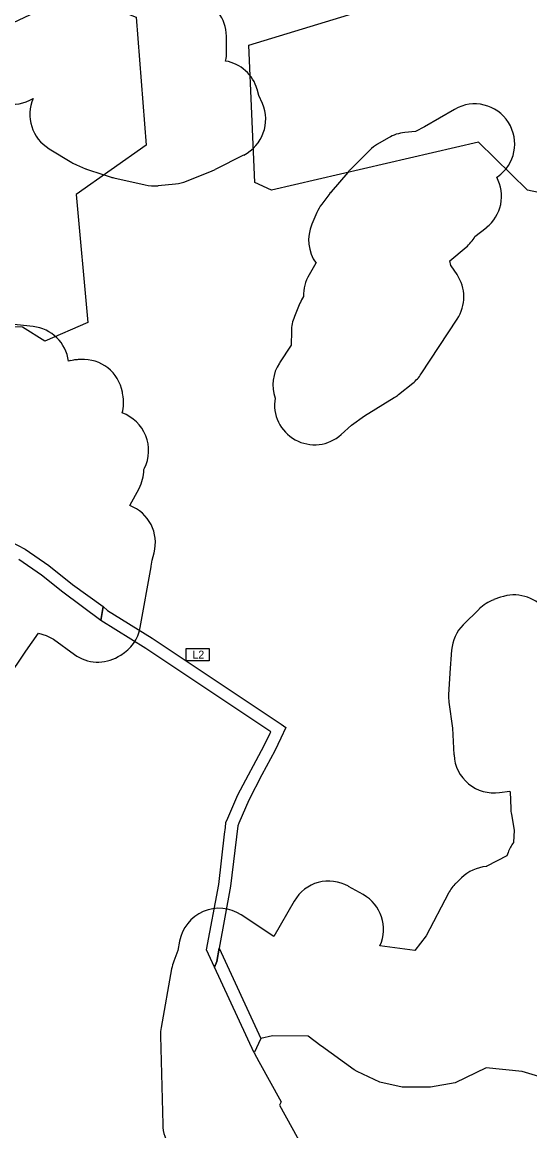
# Model space of a CAD drawing. Extents: x -547623 to -532764, y -1096714 to -1086523.
# Drawn here: x -544637 to -544003, y -1095778 to -1094393 of the extents above; entities that cross this region are included whole.
import ezdxf

# ---------------------------------------------------------------- set-up
doc = ezdxf.new("R2010")
doc.units = 0
for name, color, linetype in [('Vrstva 22', 7, 'Continuous'), ('Vrstva 23', 7, 'Continuous'), ('Vrstva 32', 7, 'Continuous'), ('Vrstva 33', 7, 'Continuous'), ('Vrstva 36', 7, 'Continuous')]:
    doc.layers.add(name, color=color, linetype=linetype)

msp = doc.modelspace()

# ---------------------------------------------------------------- linework, layer by layer
at = {"layer": 'Vrstva 22'}
for points in [[(-543560.2, -1094401.9), (-543572.9, -1094589), (-543554.8, -1094683.6), (-543653.3, -1094783), (-543676.2, -1094781), (-543835.1, -1094639.3), (-544005.7, -1094603.1), (-544067, -1094543.3), (-544325.4, -1094603.1), (-544346.2, -1094593.4), (-544353.7, -1094422.2), (-544152.6, -1094360.6), (-544163.2, -1094317.9), (-544141.9, -1094287.2), (-544146.7, -1094205.7), (-543991.6, -1094091.9), (-543560.2, -1094401.9)], [(-544569.4, -1094608.5), (-544554.7, -1094768.3), (-544608.7, -1094791.9), (-544636.4, -1094774.2), (-544680.5, -1094773.3), (-544758.2, -1094792.2), (-544897.7, -1094846.4), (-545208, -1094900.4), (-545244.6, -1094739.1), (-545204.8, -1094572.8), (-545046.9, -1094538.4), (-544985.5, -1094450.5), (-544820.5, -1094424), (-544727.5, -1094431.4), (-544569.8, -1094356.5), (-544494.7, -1094387.2), (-544482, -1094546.9), (-544569.4, -1094608.5)]]:
    msp.add_lwpolyline(points, dxfattribs=at)
at = {"layer": 'Vrstva 23'}
for p, q in [((-544381.5, -1094429.8), (-544381.7, -1094410.7)), ((-544145.7, -1094529.8), (-544159.1, -1094531.1)), ((-544179.3, -1094537.7), (-544192.9, -1094545.6)), ((-544603.2, -1094551.4), (-544574.9, -1094568.4)), ((-544395.6, -1094577.1), (-544360.1, -1094559.2)), ((-544203.1, -1094553.5), (-544227.6, -1094578.1)), ((-544569.1, -1094571.5), (-544557.6, -1094576.5)), ((-544552.7, -1094578.3), (-544526.8, -1094586.6)), ((-544522.6, -1094587.8), (-544483.3, -1094596.6)), ((-544431.8, -1094591.9), (-544399.5, -1094578.9)), ((-544230.3, -1094580.9), (-544251, -1094605.2)), ((-544467.1, -1094597.5), (-544445.3, -1094595.2)), ((-544252.8, -1094607.4), (-544262.7, -1094620.6)), ((-544268.9, -1094631.2), (-544275.1, -1094645.8)), ((-544071.4, -1094661.2), (-544057.2, -1094650)), ((-544269.9, -1094694.4), (-544278.5, -1094708.9)), ((-544093.7, -1094708.6), (-544101.1, -1094697.8)), ((-544285.5, -1094735.8), (-544285.7, -1094736.1)), ((-544289.9, -1094744.1), (-544296.9, -1094761.1)), ((-544138.5, -1094832.7), (-544093.4, -1094764.1)), ((-544623.2, -1094773.5), (-544659.1, -1094769.7)), ((-544572.9, -1094815.5), (-544576.1, -1094816.1)), ((-544563.6, -1094814.6), (-544566.8, -1094814.8)), ((-544166.7, -1094858.5), (-544148.9, -1094844.1)), ((-544484.9, -1094952.2), (-544484.1, -1094950.5)), ((-544502.4, -1094997), (-544490.9, -1094975.6)), ((-544489.5, -1095149.4), (-544475.8, -1095073.4)), ((-544039.3, -1095111.6), (-544047.6, -1095114.6)), ((-544066.1, -1095126.3), (-544086, -1095146.1)), ((-544100.5, -1095177.7), (-544102.7, -1095205.8)), ((-544517, -1095185.8), (-544513.5, -1095183.8)), ((-544102.8, -1095206.8), (-544104.3, -1095233)), ((-544211, -1095483), (-544229.2, -1095472.7)), ((-544088.1, -1095461.9), (-544095, -1095468.6)), ((-544297.2, -1095491.1), (-544322.7, -1095535.4)), ((-544322.7, -1095535.4), (-544363.3, -1095508.4)), ((-544450.2, -1095575.7), (-544463.4, -1095649.1)), ((-544464.2, -1095659.2), (-544461.4, -1095770))]:
    msp.add_line(p, q, dxfattribs=at)
for points in [[(-544336.8, -1094494.8), (-544341.1, -1094484.7), (-544343.3, -1094477.2)], [(-544096.9, -1094502.2), (-544134.2, -1094523.9), (-544145.7, -1094529.8)], [(-544044.1, -1094587.1), (-544043.1, -1094586.3)], [(-544101.5, -1094697.1), (-544102.6, -1094691.4), (-544082.5, -1094674.4)], [(-544300.6, -1094779.2), (-544301, -1094796.7), (-544315.6, -1094819)], [(-544511.1, -1094858.6), (-544511.4, -1094856.9), (-544511.6, -1094855.5)], [(-544238.3, -1094908.3), (-544225.4, -1094896.8), (-544209.2, -1094884.9), (-544172.1, -1094862.3)], [(-544475.7, -1095072.7), (-544474.5, -1095065.3), (-544472.1, -1095056.3)], [(-544671.5, -1095246.6), (-544663, -1095225.6), (-544656.1, -1095214.5), (-544632.5, -1095179), (-544616.6, -1095156.5), (-544606.9, -1095159.2), (-544597.9, -1095164.1), (-544571.6, -1095183.1)], [(-544103.9, -1095242.8), (-544099.4, -1095275.3), (-544097.6, -1095308.6)], [(-544040.6, -1095355.4), (-544028, -1095353.6), (-544027.4, -1095354.6), (-544026.6, -1095375.5)], [(-544025.8, -1095382.8), (-544022.3, -1095402.4), (-544023.3, -1095418)], [(-544029.9, -1095430.3), (-544031.4, -1095434.4), (-544056.7, -1095447.6)], [(-544104.5, -1095481.3), (-544132.2, -1095534.3), (-544146.4, -1095552.6), (-544190, -1095546.8)], [(-544440.2, -1095541.3), (-544442.3, -1095552.9), (-544447.5, -1095566.3)]]:
    msp.add_lwpolyline(points, dxfattribs=at)
for centre, start, end in [((-544431.7, -1094411.2), 0.569, 73.1837), ((-544431.5, -1094430.3), 346.6228, 0.569), ((-544391.3, -1094491.2), 16.2539, 80.278), ((-544649.3, -1094445.9), 216.0604, 301.6028), ((-544577.3, -1094508.6), 156.3156, 238.8279), ((-544382.7, -1094514.6), 296.8034, 23.3274), ((-544071.7, -1094545.4), 304.9305, 120.2555), ((-544154.1, -1094580.9), 95.7604, 120.2827), ((-544167.7, -1094588.8), 120.2827, 135.07), ((-544549.1, -1094525.7), 238.8279, 246.3706), ((-544537.5, -1094530.7), 246.3706, 252.2842), ((-544511.6, -1094539), 252.2842, 257.3321), ((-544418.2, -1094532.5), 291.9175, 296.8034), ((-544192.2, -1094613.4), 135.07, 139.5446), ((-544088.2, -1094610.7), 308.3187, 28.2454), ((-544472.4, -1094547.8), 257.3321, 276.0036), ((-544450.5, -1094545.5), 276.0036, 291.9175), ((-544213, -1094637.7), 139.5446, 142.7962), ((-544222.9, -1094650.8), 142.7962, 156.9105), ((-544229.1, -1094665.4), 156.9105, 215.4106), ((-544114.7, -1094636.2), 310.1661, 329.9934), ((-544142.5, -1094725.8), 34.0665, 34.9413), ((-544235.5, -1094734.4), 149.3079, 181.5851), ((-544135.2, -1094736.6), 326.639, 34.0665), ((-544243.6, -1094763.1), 147.2549, 157.6487), ((-544250.6, -1094780.1), 157.6487, 178.8948), ((-544628.6, -1094823.2), 7.5163, 83.8546), ((-544567.2, -1094865.3), 100.225, 103.6855), ((-544564, -1094864.7), 93.2095, 100.225), ((-544560.8, -1094864.5), 10.3889, 93.2095), ((-544273.7, -1094846.4), 146.8451, 199.0947), ((-544180.3, -1094805.2), 308.8939, 326.639), ((-544560.1, -1094868.4), 344.9547, 11.3099), ((-544271.7, -1094871.1), 170.3942, 311.8076), ((-544198.1, -1094819.6), 301.3801, 308.8939), ((-544529, -1094928.4), 333.7195, 69.9207), ((-544534.9, -1094952), 331.8145, 359.7902), ((-544520.5, -1095043.6), 345.3089, 68.7265), ((-544525.1, -1095064.6), 349.7927, 350.6729), ((-544022.4, -1095158.7), 39.675, 109.7016), ((-544030.8, -1095161.7), 109.7016, 134.8702), ((-544538.7, -1095140.6), 300.2869, 349.7927), ((-544050.7, -1095181.5), 134.8702, 175.6075), ((-544542.2, -1095142.6), 234.0894, 300.2869), ((-544052.8, -1095209.6), 175.6075, 176.7295), ((-544054.3, -1095235.9), 176.7295, 187.9009), ((-544047.6, -1095305.9), 183.0927, 278.0616), ((-543976.7, -1095373.8), 181.9744, 190.3322), ((-543983, -1095447.6), 143.7295, 159.7953), ((-544053.3, -1095497.8), 94.6652, 134.1575), ((-544033.5, -1095491.9), 117.6654, 118.5636), ((-544253.9, -1095516.1), 60.3534, 150.0364), ((-544060.2, -1095504.5), 134.1575, 152.3533), ((-544235.7, -1095526.5), 336.0277, 60.3534), ((-544391, -1095550), 56.3675, 169.8993), ((-544401, -1095584.5), 158.5572, 169.7687), ((-544414.2, -1095657.9), 169.7687, 181.4263), ((-544411.4, -1095768.8), 181.4263, 317.8953)]:
    msp.add_arc(centre, 50, start, end, dxfattribs=at)
at = {"layer": 'Vrstva 32'}
for points in [[(-544262.9, -1095672.3), (-544263.7, -1095671.7), (-544279.7, -1095660), (-544324.2, -1095659.4), (-544338.6, -1095662.6), (-544347, -1095680.5), (-544341.3, -1095691.5), (-544313.2, -1095741.8), (-544315.5, -1095746.1), (-544277.8, -1095813.9), (-544276.1, -1095826.4), (-544267.8, -1095831.7), (-544243.7, -1095841.7), (-544217.4, -1095853.4), (-544166.3, -1095879.5), (-544135.1, -1095899.1), (-544106, -1095928.4), (-543909.4, -1095790.9)], [(-543939.1, -1095725.8), (-544012.2, -1095704.1), (-544057.3, -1095699.3), (-544096, -1095718.2), (-544126.8, -1095723.3), (-544162.1, -1095723.3), (-544190.1, -1095717.2), (-544218.4, -1095703.9), (-544222.4, -1095702), (-544262.9, -1095672.3)]]:
    msp.add_lwpolyline(points, dxfattribs=at)
at = {"layer": 'Vrstva 33'}
for points in [[(-544661.7, -1095036.7), (-544633.2, -1095051.5), (-544603.7, -1095071.8), (-544574, -1095095.7), (-544535.6, -1095123.3), (-544538.7, -1095140.6), (-544586.2, -1095105.1), (-544612.7, -1095083.9), (-544641, -1095064.4)], [(-544383.1, -1095399.1), (-544382.4, -1095392.8), (-544379.9, -1095387.5), (-544367.4, -1095358.4), (-544334.5, -1095296.6), (-544327.3, -1095281.4), (-544326.4, -1095279.5), (-544482.5, -1095175.5), (-544538.7, -1095140.6), (-544535.6, -1095123.3)], [(-544535.6, -1095123.3), (-544530.3, -1095128.2), (-544474.4, -1095162.9), (-544313.5, -1095270)], [(-544313.5, -1095270), (-544307.4, -1095274.1), (-544313.7, -1095287.8), (-544321.1, -1095303.4), (-544337.7, -1095333.2), (-544353.9, -1095364.9), (-544366.2, -1095393.6)], [(-544366.2, -1095393.6), (-544367.7, -1095396.9), (-544376.6, -1095472.6), (-544391, -1095550), (-544393.9, -1095566.6), (-544396.6, -1095573.5)], [(-544384.1, -1095407.4), (-544383.1, -1095399.1)], [(-544396.6, -1095573.5), (-544406.6, -1095552), (-544391.4, -1095470.4), (-544384.1, -1095407.4)], [(-544396.6, -1095573.5), (-544393.9, -1095566.6), (-544391, -1095550), (-544338.6, -1095662.6), (-544347, -1095680.5), (-544396.6, -1095573.5)]]:
    msp.add_lwpolyline(points, dxfattribs=at)
at = {"layer": 'Vrstva 36'}
msp.add_lwpolyline([(-544431.9, -1095175.6), (-544403.3, -1095175.6), (-544403.3, -1095191), (-544431.9, -1095191)], close=True, dxfattribs=at)

# ---------------------------------------------------------------- texts
msp.add_text('L2', height=10, dxfattribs=at).set_placement((-544424.4, -1095188.3))

doc.saveas('drawing.dxf')
